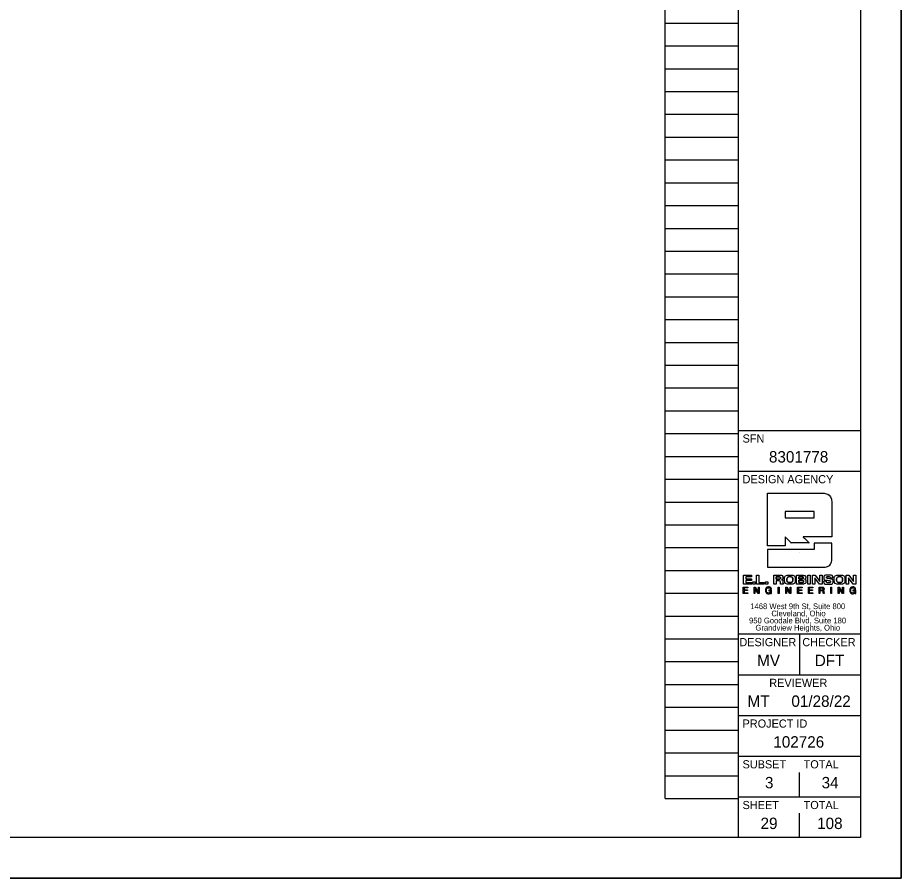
# Model space of a CAD drawing. Extents: x -20.1 to 34, y 0 to 22.
# Drawn here: x 23.15 to 34, y 0 to 10.57 of the extents above; entities that cross this region are included whole.
import ezdxf

# ---------------------------------------------------------------- set-up
doc = ezdxf.new("R2010")
doc.units = 0
for name, color, linetype in [('SC_Scratch1', 7, 'Continuous'), ('SH_Border', 7, 'Continuous'), ('SH_Cut_Line', 7, 'Continuous'), ('SH_Data', 7, 'Continuous')]:
    doc.layers.add(name, color=color, linetype=linetype)

msp = doc.modelspace()

# ---------------------------------------------------------------- linework, layer by layer
at = {"layer": 'SC_Scratch1'}
for p, q in [((31.1, 0.98), (31.1, 21.14)), ((32, 0.98), (32, 21.14)), ((31.1, 10.5), (32, 10.5)), ((31.1, 10.22), (32, 10.22)), ((31.1, 9.94), (32, 9.94)), ((31.1, 9.66), (32, 9.66)), ((31.1, 9.38), (32, 9.38)), ((31.1, 9.1), (32, 9.1)), ((31.1, 8.82), (32, 8.82)), ((31.1, 8.54), (32, 8.54)), ((31.1, 8.26), (32, 8.26)), ((31.1, 7.98), (32, 7.98)), ((31.1, 7.7), (32, 7.7)), ((31.1, 7.42), (32, 7.42)), ((31.1, 7.14), (32, 7.14)), ((31.1, 6.86), (32, 6.86)), ((31.1, 6.58), (32, 6.58)), ((31.1, 6.3), (32, 6.3)), ((31.1, 6.02), (32, 6.02)), ((31.1, 5.74), (32, 5.74)), ((31.1, 5.46), (32, 5.46)), ((31.1, 5.18), (32, 5.18)), ((31.1, 4.9), (32, 4.9)), ((31.1, 4.62), (32, 4.62)), ((31.1, 4.34), (32, 4.34)), ((31.1, 4.06), (32, 4.06)), ((31.1, 3.78), (32, 3.78)), ((31.1, 3.5), (32, 3.5)), ((31.1, 3.22), (32, 3.22)), ((31.1, 2.94), (32, 2.94)), ((31.1, 2.66), (32, 2.66)), ((31.1, 2.38), (32, 2.38)), ((31.1, 2.1), (32, 2.1)), ((31.1, 1.82), (32, 1.82)), ((31.1, 1.54), (32, 1.54)), ((31.1, 1.26), (32, 1.26)), ((31.1, 0.98), (32, 0.98))]:
    msp.add_line(p, q, dxfattribs=at)
msp.add_lwpolyline([(0, 22), (34, 22), (34, 0), (0, 0)], close=True, dxfattribs=at)
at = {"layer": 'SH_Border'}
for p, q in [((32, 0.5), (32, 21.5)), ((32, 5.5), (33.5, 5.5)), ((32, 5), (33.5, 5)), ((32, 3), (33.5, 3)), ((32.75, 3), (32.75, 2.5)), ((32, 2.5), (33.5, 2.5)), ((32, 2), (33.5, 2)), ((32, 1.5), (33.5, 1.5)), ((32, 1), (33.5, 1))]:
    msp.add_line(p, q, dxfattribs=at)
msp.add_lwpolyline([(1.5, 21.5), (33.5, 21.5), (33.5, 0.5), (1.5, 0.5)], close=True, dxfattribs=at)
at = {"layer": 'SH_Cut_Line'}
msp.add_lwpolyline([(0, 0), (34, 0), (34, 22), (0, 22)], close=True, dxfattribs=at)
at = {"layer": 'SH_Data'}
for p, q in [((32.929, 4.503), (32.574, 4.503)), ((32.574, 4.503), (32.574, 4.425)), ((32.929, 4.425), (32.929, 4.503)), ((32.574, 4.425), (32.929, 4.425)), ((32.75, 4), (32.75, 4)), ((32.463, 3.701), (32.463, 3.673)), ((32.743, 3.702), (32.743, 3.678)), ((32.743, 3.659), (32.743, 3.633)), ((33.001, 3.566), (33.001, 3.539)), ((33.001, 3.539), (33.023, 3.539)), ((32.75, 1), (32.75, 1.3)), ((32.75, 0.5), (32.75, 0.8)), ((32.375, 0.675), (32.375, 0.675))]:
    msp.add_line(p, q, dxfattribs=at)
for points in [[(32.06, 3.721), (32.161, 3.721), (32.161, 3.701), (32.089, 3.701), (32.089, 3.678), (32.158, 3.678), (32.158, 3.658), (32.089, 3.658), (32.089, 3.633), (32.162, 3.633), (32.162, 3.613), (32.06, 3.613), (32.06, 3.721)], [(32.22, 3.721), (32.249, 3.721), (32.249, 3.634), (32.316, 3.634), (32.316, 3.613), (32.22, 3.613), (32.22, 3.721)], [(32.851, 3.721), (32.881, 3.721), (32.881, 3.613), (32.851, 3.613), (32.851, 3.721)], [(32.999, 3.721), (33.027, 3.721), (33.027, 3.613), (32.995, 3.613), (32.936, 3.689), (32.936, 3.689), (32.936, 3.613), (32.907, 3.613), (32.907, 3.721), (32.941, 3.721), (32.999, 3.646), (32.999, 3.646), (32.999, 3.721)], [(33.413, 3.721), (33.442, 3.721), (33.442, 3.613), (33.41, 3.613), (33.35, 3.689), (33.35, 3.689), (33.35, 3.613), (33.321, 3.613), (33.321, 3.721), (33.356, 3.721), (33.413, 3.646), (33.413, 3.646), (33.413, 3.721)], [(32.175, 3.639), (32.205, 3.639), (32.205, 3.613), (32.175, 3.613), (32.175, 3.639)], [(32.331, 3.639), (32.361, 3.639), (32.361, 3.613), (32.331, 3.613), (32.331, 3.639)], [(32.059, 3.575), (32.114, 3.575), (32.114, 3.566), (32.07, 3.566), (32.07, 3.541), (32.111, 3.541), (32.111, 3.532), (32.07, 3.532), (32.07, 3.505), (32.114, 3.505), (32.114, 3.496), (32.059, 3.496), (32.059, 3.575)], [(32.191, 3.575), (32.203, 3.575), (32.244, 3.511), (32.244, 3.511), (32.244, 3.575), (32.254, 3.575), (32.254, 3.496), (32.243, 3.496), (32.202, 3.559), (32.201, 3.559), (32.201, 3.496), (32.191, 3.496), (32.191, 3.575)], [(32.487, 3.575), (32.498, 3.575), (32.498, 3.496), (32.487, 3.496), (32.487, 3.575)], [(32.581, 3.575), (32.592, 3.575), (32.633, 3.511), (32.633, 3.511), (32.633, 3.575), (32.643, 3.575), (32.643, 3.496), (32.632, 3.496), (32.591, 3.559), (32.591, 3.559), (32.591, 3.496), (32.581, 3.496), (32.581, 3.575)], [(32.726, 3.575), (32.781, 3.575), (32.781, 3.566), (32.737, 3.566), (32.737, 3.541), (32.778, 3.541), (32.778, 3.532), (32.737, 3.532), (32.737, 3.505), (32.781, 3.505), (32.781, 3.496), (32.726, 3.496), (32.726, 3.575)], [(32.859, 3.575), (32.913, 3.575), (32.913, 3.566), (32.869, 3.566), (32.869, 3.541), (32.91, 3.541), (32.91, 3.532), (32.869, 3.532), (32.869, 3.505), (32.913, 3.505), (32.913, 3.496), (32.859, 3.496), (32.859, 3.575)], [(33.133, 3.575), (33.143, 3.575), (33.143, 3.496), (33.133, 3.496), (33.133, 3.575)], [(33.226, 3.575), (33.237, 3.575), (33.279, 3.511), (33.279, 3.511), (33.279, 3.575), (33.289, 3.575), (33.289, 3.496), (33.277, 3.496), (33.236, 3.559), (33.236, 3.559), (33.236, 3.496), (33.226, 3.496), (33.226, 3.575)]]:
    msp.add_lwpolyline(points, dxfattribs=at)
for points, degree in [([(32.356, 4.083), (32.356, 4.086), (32.356, 4.724), (32.356, 4.727)], 2), ([(32.356, 4.727), (32.36, 4.727), (33.03, 4.727), (33.034, 4.727), (33.096, 4.727), (33.147, 4.677), (33.147, 4.614)], 3), ([(33.147, 4.614), (33.147, 4.612), (33.147, 4.194), (33.147, 4.192)], 2), ([(32.645, 4.121), (32.645, 4.121), (32.574, 4.191), (32.574, 4.192)], 2), ([(32.574, 4.192), (32.574, 4.191), (32.574, 4.083), (32.574, 4.083)], 2), ([(33.147, 4.192), (33.145, 4.192), (32.795, 4.192), (32.793, 4.192)], 2), ([(32.793, 4.192), (32.793, 4.191), (32.866, 4.121), (32.866, 4.121)], 2), ([(32.929, 4.115), (32.929, 4.115), (33.147, 4.115), (33.147, 4.115), (33.147, 4.115), (33.147, 3.933), (33.147, 3.933), (33.147, 3.87), (33.096, 3.82), (33.034, 3.82), (33.034, 3.82), (32.356, 3.82), (32.356, 3.82), (32.356, 3.82), (32.356, 4.037), (32.356, 4.037), (32.356, 4.037), (32.929, 4.037), (32.929, 4.037), (32.929, 4.037), (32.929, 4.115), (32.929, 4.115)], 3), ([(32.574, 4.083), (32.573, 4.083), (32.357, 4.083), (32.356, 4.083)], 2), ([(32.866, 4.121), (32.865, 4.121), (32.646, 4.121), (32.645, 4.121)], 2), ([(32.433, 3.613), (32.433, 3.613), (32.433, 3.721), (32.433, 3.721)], 2), ([(32.433, 3.721), (32.433, 3.721), (32.512, 3.721), (32.512, 3.721), (32.542, 3.721), (32.545, 3.703), (32.546, 3.692)], 3), ([(32.463, 3.673), (32.463, 3.673), (32.502, 3.673), (32.502, 3.673), (32.508, 3.673), (32.516, 3.677), (32.516, 3.687), (32.516, 3.698), (32.507, 3.701), (32.5, 3.701), (32.5, 3.701), (32.463, 3.701), (32.463, 3.701), (32.463, 3.701), (32.463, 3.673), (32.463, 3.673)], 3), ([(32.463, 3.673), (32.476, 3.673), (32.489, 3.673), (32.508, 3.673), (32.516, 3.677), (32.516, 3.698), (32.507, 3.701), (32.488, 3.701), (32.475, 3.701), (32.463, 3.701)], 3), ([(32.546, 3.692), (32.544, 3.679), (32.542, 3.67), (32.53, 3.666)], 2), ([(32.631, 3.61), (32.573, 3.61), (32.567, 3.645), (32.565, 3.667), (32.564, 3.69), (32.573, 3.724), (32.631, 3.724)], 3), ([(32.631, 3.63), (32.658, 3.63), (32.667, 3.65), (32.667, 3.667), (32.667, 3.684), (32.658, 3.704), (32.631, 3.704), (32.604, 3.704), (32.595, 3.684), (32.595, 3.667), (32.595, 3.65), (32.604, 3.63), (32.631, 3.63)], 3), ([(32.631, 3.704), (32.604, 3.704), (32.595, 3.684), (32.595, 3.667), (32.595, 3.65), (32.604, 3.63), (32.631, 3.63)], 3), ([(32.631, 3.724), (32.69, 3.724), (32.695, 3.689), (32.697, 3.667), (32.699, 3.644), (32.69, 3.61), (32.631, 3.61)], 3), ([(32.631, 3.63), (32.658, 3.63), (32.667, 3.65), (32.667, 3.667), (32.667, 3.684), (32.658, 3.704), (32.631, 3.704)], 3), ([(32.714, 3.613), (32.714, 3.613), (32.714, 3.721), (32.714, 3.721)], 2), ([(32.714, 3.721), (32.714, 3.721), (32.795, 3.721), (32.795, 3.721)], 2), ([(32.743, 3.678), (32.743, 3.678), (32.784, 3.678), (32.784, 3.678), (32.791, 3.678), (32.796, 3.682), (32.796, 3.69), (32.796, 3.697), (32.793, 3.702), (32.78, 3.702), (32.78, 3.702), (32.743, 3.702), (32.743, 3.702), (32.743, 3.702), (32.743, 3.678), (32.743, 3.678)], 3), ([(32.743, 3.678), (32.757, 3.678), (32.771, 3.678), (32.791, 3.681), (32.791, 3.683), (32.792, 3.697), (32.793, 3.702), (32.768, 3.702), (32.756, 3.702), (32.743, 3.702)], 3), ([(32.795, 3.721), (32.81, 3.718), (32.826, 3.714), (32.826, 3.694)], 2), ([(32.826, 3.694), (32.824, 3.686), (32.822, 3.675), (32.812, 3.672)], 2), ([(33.126, 3.69), (33.124, 3.704), (33.111, 3.706), (33.099, 3.706), (33.087, 3.706), (33.079, 3.7), (33.079, 3.693), (33.079, 3.687), (33.084, 3.684), (33.091, 3.683), (33.091, 3.683), (33.128, 3.677), (33.128, 3.677), (33.148, 3.673), (33.163, 3.666), (33.163, 3.646), (33.163, 3.626), (33.149, 3.61), (33.107, 3.61), (33.08, 3.61), (33.046, 3.613), (33.045, 3.647), (33.045, 3.647), (33.079, 3.647), (33.079, 3.647), (33.079, 3.632), (33.094, 3.629), (33.107, 3.629), (33.121, 3.629), (33.13, 3.634), (33.13, 3.643), (33.13, 3.651), (33.123, 3.654), (33.112, 3.655), (33.112, 3.655), (33.085, 3.66), (33.085, 3.66), (33.066, 3.662), (33.047, 3.668), (33.047, 3.69), (33.047, 3.715), (33.067, 3.724), (33.101, 3.724), (33.124, 3.724), (33.157, 3.721), (33.159, 3.69), (33.159, 3.69), (33.126, 3.69), (33.126, 3.69)], 3), ([(33.242, 3.61), (33.183, 3.61), (33.178, 3.645), (33.176, 3.667), (33.174, 3.69), (33.183, 3.724), (33.242, 3.724)], 3), ([(33.242, 3.63), (33.269, 3.63), (33.278, 3.65), (33.278, 3.667), (33.278, 3.684), (33.269, 3.704), (33.242, 3.704), (33.215, 3.704), (33.205, 3.684), (33.205, 3.667), (33.205, 3.65), (33.215, 3.63), (33.242, 3.63)], 3), ([(33.242, 3.704), (33.215, 3.704), (33.205, 3.684), (33.205, 3.667), (33.205, 3.65), (33.215, 3.63), (33.242, 3.63)], 3), ([(33.242, 3.724), (33.3, 3.724), (33.306, 3.689), (33.308, 3.667), (33.309, 3.644), (33.3, 3.61), (33.242, 3.61)], 3), ([(33.242, 3.63), (33.269, 3.63), (33.278, 3.65), (33.278, 3.667), (33.278, 3.684), (33.269, 3.704), (33.242, 3.704)], 3), ([(32.463, 3.613), (32.462, 3.613), (32.433, 3.613), (32.433, 3.613)], 2), ([(32.499, 3.653), (32.499, 3.653), (32.463, 3.653), (32.463, 3.653)], 2), ([(32.463, 3.653), (32.463, 3.652), (32.463, 3.613), (32.463, 3.613)], 2), ([(32.518, 3.613), (32.516, 3.618), (32.516, 3.622), (32.516, 3.634), (32.515, 3.649), (32.508, 3.65), (32.499, 3.653)], 3), ([(32.55, 3.613), (32.55, 3.613), (32.518, 3.613), (32.518, 3.613)], 2), ([(32.53, 3.666), (32.53, 3.666), (32.53, 3.665), (32.53, 3.665)], 2), ([(32.53, 3.665), (32.543, 3.663), (32.544, 3.647), (32.544, 3.636)], 2), ([(32.544, 3.636), (32.544, 3.631), (32.548, 3.619), (32.55, 3.613)], 2), ([(32.829, 3.645), (32.827, 3.632), (32.824, 3.613), (32.791, 3.613), (32.791, 3.613), (32.714, 3.613), (32.714, 3.613)], 3), ([(32.743, 3.633), (32.743, 3.633), (32.787, 3.633), (32.787, 3.633), (32.796, 3.633), (32.8, 3.639), (32.8, 3.646), (32.8, 3.655), (32.794, 3.659), (32.784, 3.659), (32.784, 3.659), (32.743, 3.659), (32.743, 3.659), (32.743, 3.659), (32.743, 3.633), (32.743, 3.633)], 3), ([(32.743, 3.633), (32.758, 3.633), (32.772, 3.633), (32.796, 3.633), (32.8, 3.639), (32.8, 3.655), (32.794, 3.659), (32.77, 3.659), (32.757, 3.659), (32.743, 3.659)], 3), ([(32.812, 3.672), (32.812, 3.672), (32.812, 3.672), (32.812, 3.672)], 2), ([(32.812, 3.672), (32.824, 3.67), (32.827, 3.656), (32.829, 3.645)], 2), ([(32.396, 3.506), (32.39, 3.498), (32.38, 3.494), (32.37, 3.494), (32.347, 3.494), (32.333, 3.514), (32.333, 3.534), (32.333, 3.557), (32.346, 3.577), (32.37, 3.577), (32.388, 3.577), (32.401, 3.569), (32.404, 3.551), (32.404, 3.551), (32.394, 3.551), (32.394, 3.551), (32.392, 3.562), (32.382, 3.568), (32.37, 3.568), (32.351, 3.568), (32.344, 3.551), (32.344, 3.534), (32.344, 3.518), (32.353, 3.503), (32.37, 3.503), (32.387, 3.503), (32.396, 3.515), (32.396, 3.529), (32.396, 3.529), (32.371, 3.529), (32.371, 3.529), (32.371, 3.529), (32.371, 3.538), (32.371, 3.538), (32.371, 3.538), (32.405, 3.538), (32.405, 3.538), (32.405, 3.538), (32.405, 3.496), (32.405, 3.496), (32.405, 3.496), (32.398, 3.496), (32.398, 3.496), (32.398, 3.496), (32.396, 3.506), (32.396, 3.506)], 3), ([(32.991, 3.575), (32.991, 3.575), (33.027, 3.575), (33.028, 3.575), (33.042, 3.575), (33.051, 3.567), (33.051, 3.554)], 3), ([(32.991, 3.496), (32.991, 3.497), (32.991, 3.574), (32.991, 3.575)], 2), ([(33.001, 3.496), (33.001, 3.496), (32.991, 3.496), (32.991, 3.496)], 2), ([(33.023, 3.539), (33.033, 3.539), (33.041, 3.541), (33.041, 3.552), (33.041, 3.56), (33.037, 3.566), (33.027, 3.566), (33.027, 3.566), (33.001, 3.566), (33.001, 3.566), (33.001, 3.566), (33.001, 3.539), (33.001, 3.539), (33.001, 3.539), (33.023, 3.539), (33.023, 3.539)], 3), ([(33.023, 3.539), (33.033, 3.539), (33.041, 3.541), (33.041, 3.56), (33.037, 3.566), (33.018, 3.566), (33.01, 3.566), (33.001, 3.566)], 3), ([(33.04, 3.516), (33.038, 3.523), (33.037, 3.53), (33.027, 3.53), (33.027, 3.53), (33.001, 3.53), (33.001, 3.53)], 3), ([(33.001, 3.53), (33.001, 3.53), (33.001, 3.496), (33.001, 3.496)], 2), ([(33.051, 3.554), (33.049, 3.545), (33.047, 3.537), (33.038, 3.534)], 2), ([(33.038, 3.534), (33.038, 3.534), (33.038, 3.534), (33.038, 3.534)], 2), ([(33.038, 3.534), (33.044, 3.529), (33.047, 3.525), (33.048, 3.518)], 2), ([(33.043, 3.496), (33.042, 3.5), (33.041, 3.508), (33.04, 3.516)], 2), ([(33.054, 3.496), (33.054, 3.496), (33.043, 3.496), (33.043, 3.496)], 2), ([(33.048, 3.518), (33.049, 3.51), (33.052, 3.502), (33.054, 3.496)], 2), ([(33.43, 3.506), (33.424, 3.498), (33.414, 3.494), (33.405, 3.494), (33.382, 3.494), (33.368, 3.514), (33.368, 3.534), (33.368, 3.557), (33.38, 3.577), (33.405, 3.577), (33.422, 3.577), (33.436, 3.569), (33.439, 3.551), (33.439, 3.551), (33.429, 3.551), (33.429, 3.551), (33.426, 3.562), (33.417, 3.568), (33.405, 3.568), (33.386, 3.568), (33.378, 3.551), (33.378, 3.534), (33.378, 3.518), (33.388, 3.503), (33.405, 3.503), (33.421, 3.503), (33.431, 3.515), (33.43, 3.529), (33.43, 3.529), (33.405, 3.529), (33.405, 3.529), (33.405, 3.529), (33.405, 3.538), (33.405, 3.538), (33.405, 3.538), (33.44, 3.538), (33.44, 3.538), (33.44, 3.538), (33.44, 3.496), (33.44, 3.496), (33.44, 3.496), (33.433, 3.496), (33.433, 3.496), (33.433, 3.496), (33.43, 3.506), (33.43, 3.506)], 3)]:
    msp.add_open_spline(points, degree=degree, dxfattribs=at)

# ---------------------------------------------------------------- texts
for s, height, p in [('SFN', 0.1, (32.05, 5.35)), ('8301778', 0.14, (32.374, 5.105)), ('DESIGN AGENCY', 0.1, (32.05, 4.85)), ('1468 West 9th St, Suite 800', 0.07, (32.145, 3.305)), ('Cleveland, Ohio', 0.07, (32.404, 3.217)), ('950 Goodale Blvd, Suite 180', 0.07, (32.13, 3.13)), ('Grandview Heights, Ohio', 0.07, (32.208, 3.042)), ('DESIGNER', 0.1, (32.011, 2.85)), ('CHECKER', 0.1, (32.784, 2.85)), ('MV', 0.14, (32.229, 2.605)), ('DFT', 0.14, (32.937, 2.605)), ('REVIEWER', 0.1, (32.378, 2.35)), ('MT', 0.14, (32.111, 2.105)), ('01/28/22', 0.14, (32.65, 2.105)), ('PROJECT ID', 0.1, (32.05, 1.85)), ('102726', 0.14, (32.428, 1.605)), ('SUBSET', 0.1, (32.05, 1.35)), ('TOTAL', 0.1, (32.8, 1.35)), ('3', 0.14, (32.325, 1.105)), ('34', 0.14, (33.021, 1.105)), ('SHEET', 0.1, (32.05, 0.85)), ('TOTAL', 0.1, (32.8, 0.85)), ('29', 0.14, (32.271, 0.605)), ('108', 0.14, (32.966, 0.605))]:
    msp.add_text(s, height=height, dxfattribs=at).set_placement(p)

doc.saveas('drawing.dxf')
